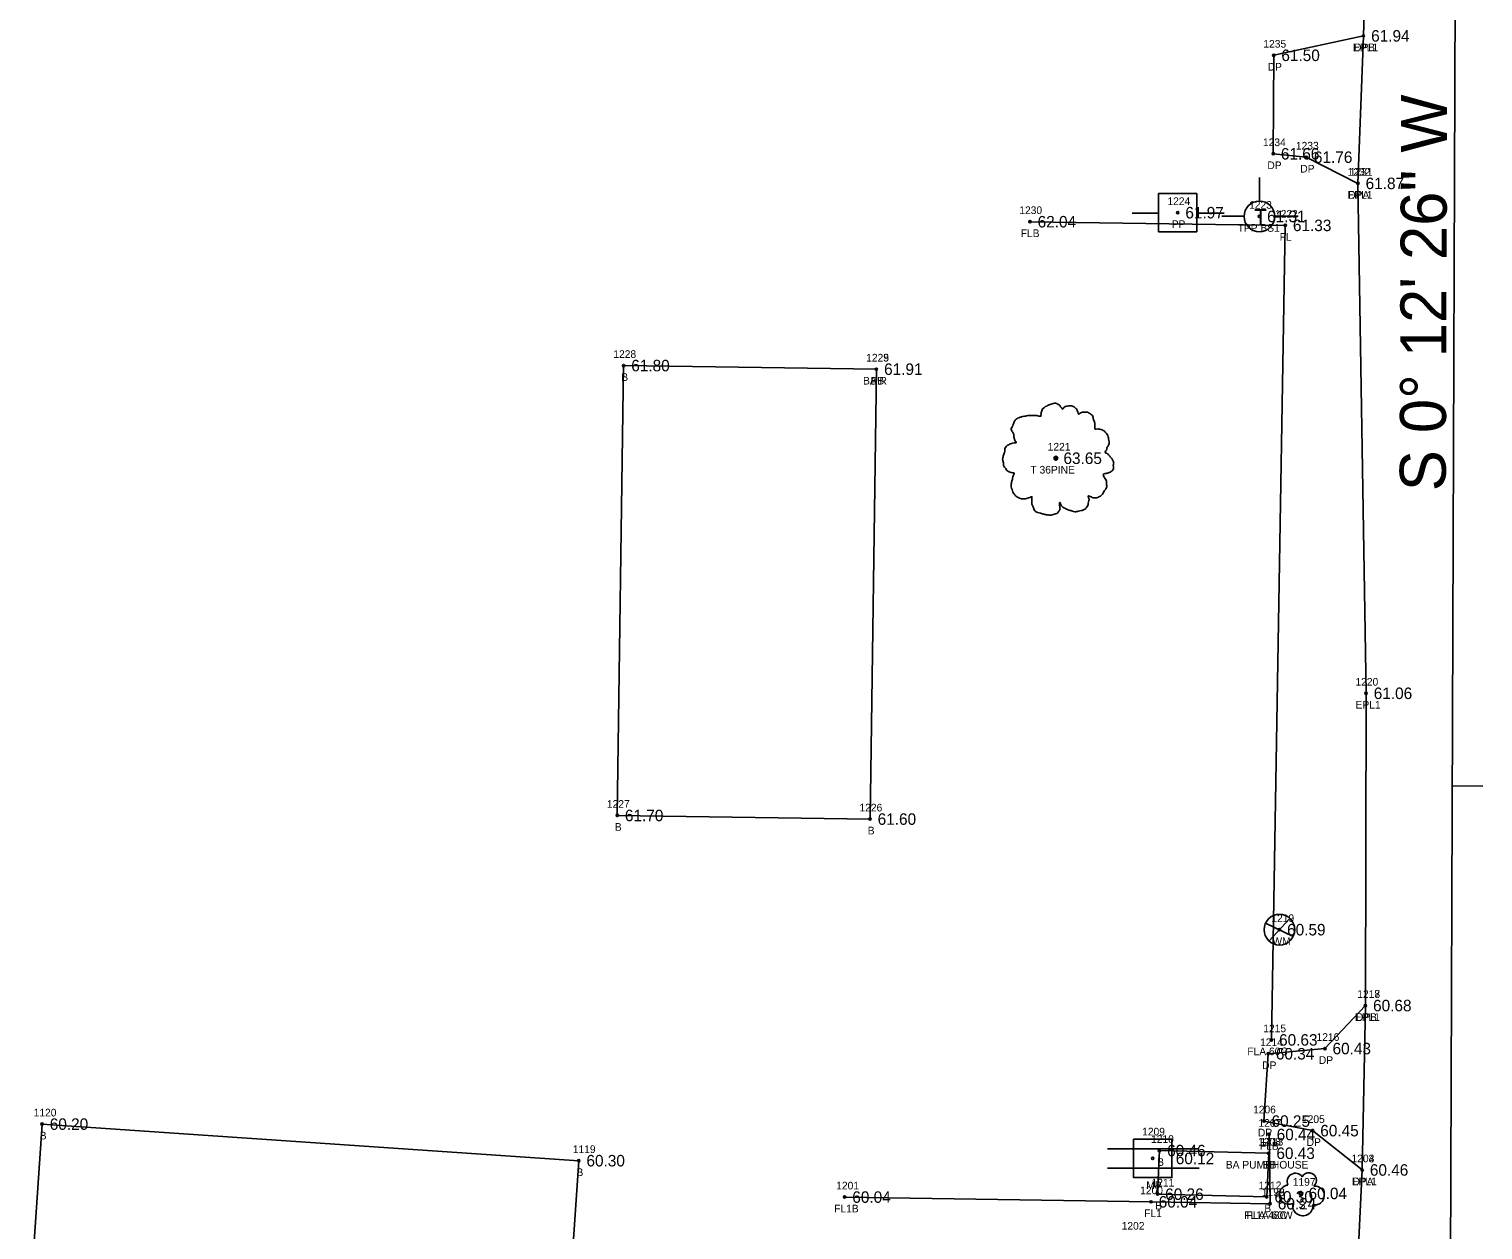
# Model space of a CAD drawing. Extents: x 2420113 to 2422887, y 845323 to 846653.
# Drawn here: x 2420774.1 to 2420963.9, y 845827.5 to 845984.2 of the extents above; entities that cross this region are included whole.
import ezdxf

# ---------------------------------------------------------------- set-up
doc = ezdxf.new("R2010")
doc.units = 0
for name, color, linetype in [('RD_EX_Bldg', 7, 'Continuous'), ('RD_EX_Bldg_txCode', 7, 'Continuous'), ('RD_EX_Driveway', 7, 'Continuous'), ('RD_EX_Driveway_txCode', 7, 'Continuous'), ('RD_EX_Fence_Other', 7, 'Continuous'), ('RD_EX_Fence_Other_txCode', 7, 'Continuous'), ('RD_EX_Road', 7, 'Continuous'), ('RD_EX_Road_txCode', 7, 'Continuous'), ('RD_EX_TX_Bldg_ELEV', 7, 'Continuous'), ('RD_EX_TX_Driveway_ELEV', 7, 'Continuous'), ('RD_EX_TX_Fence_Other_ELEV', 7, 'Continuous'), ('RD_EX_TX_Road_ELEV', 7, 'Continuous'), ('RD_EX_TX_UT_ELEV', 7, 'Continuous'), ('RD_EX_TX_VEG_ELEV', 7, 'Continuous'), ('RD_EX_UT', 7, 'Continuous'), ('RD_EX_UT_txCode', 7, 'Continuous'), ('RD_EX_VEG', 7, 'Continuous'), ('RD_EX_VEG_txCode', 7, 'Continuous'), ('RD_HC_Cl', 7, 'Continuous'), ('RD_HC_Data', 7, 'Continuous'), ('RD_HC_Data_Tic', 7, 'Continuous'), ('RD_HC_Survey_ELEV', 7, 'Continuous'), ('RD_SMD_Locator', 7, 'Continuous')]:
    doc.layers.add(name, color=color, linetype=linetype)

msp = doc.modelspace()

# ---------------------------------------------------------------- linework, layer by layer
at = {"layer": 'RD_EX_Bldg'}
for points in [[(2420884.74, 845939.79), (2420883.9, 845881.09), (2420850.91, 845881.56), (2420851.74, 845940.26), (2420884.74, 845939.79)], [(2420774.14, 845816.35), (2420844.19, 845811.58), (2420845.89, 845836.52), (2420775.84, 845841.29), (2420774.14, 845816.35)], [(2420935.94, 845837.49), (2420921.68, 845837.84), (2420921.43, 845832.15), (2420935.68, 845831.8), (2420935.94, 845837.49)]]:
    msp.add_lwpolyline(points, dxfattribs=at)
at = {"layer": 'RD_EX_Driveway'}
for points in [[(2420947.59, 845964.03), (2420940.84, 845967.45), (2420936.53, 845967.89), (2420936.59, 845980.74), (2420948.31, 845983.28)], [(2420948.14, 845835.31), (2420941.67, 845840.44), (2420935.31, 845841.69), (2420935.87, 845850.47), (2420943.27, 845851.15), (2420948.56, 845856.76)]]:
    msp.add_lwpolyline(points, dxfattribs=at)
at = {"layer": 'RD_EX_Fence_Other'}
msp.add_line((2420936.12, 845830.91), (2420935.98, 845839.94), dxfattribs=at)
for points in [[(2420936.29, 845852.28), (2420938.1, 845958.55), (2420904.78, 845959.03)], [(2420936.12, 845830.91), (2420920.58, 845831.15), (2420880.59, 845831.77)]]:
    msp.add_lwpolyline(points, dxfattribs=at)
at = {"layer": 'RD_EX_Road'}
msp.add_lwpolyline([(2420911.08, 845716.87), (2420926.22, 845723.04), (2420936.01, 845731.06), (2420942.67, 845742.11), (2420946.54, 845756.04), (2420945.56, 845775.49), (2420946.2, 845794.55), (2420948.14, 845835.31), (2420948.56, 845856.76), (2420948.65, 845897.5), (2420947.59, 845964.03), (2420948.31, 845983.28), (2420948.75, 845998.25), (2420949.7, 846105.56), (2420949.53, 846120.86), (2420949.28, 846141.3), (2420949.41, 846199.43)], dxfattribs=at)
at = {"layer": 'RD_EX_UT'}
for p, q in [((2420934.73, 845964.79), (2420934.73, 845961.72)), ((2420926.55, 845962.72), (2420921.55, 845962.72)), ((2420921.55, 845962.72), (2420921.55, 845957.72)), ((2420926.55, 845957.72), (2420926.55, 845962.72)), ((2420918.12, 845960.16), (2420921.59, 845960.16)), ((2420926.48, 845960.16), (2420930.12, 845960.16)), ((2420929.8, 845959.74), (2420932.73, 845959.74)), ((2420936.73, 845959.74), (2420939.8, 845959.74)), ((2420921.55, 845957.72), (2420926.55, 845957.72)), ((2420935.99, 845865.2), (2420938.65, 845868.09)), ((2420935.51, 845867.49), (2420939.14, 845865.78)), ((2420914.88, 845838.06), (2420926.88, 845838.06)), ((2420914.88, 845835.56), (2420926.88, 845835.56))]:
    msp.add_line(p, q, dxfattribs=at)
msp.add_lwpolyline([(2420918.31, 845839.31), (2420923.31, 845839.31), (2420923.31, 845834.31), (2420918.31, 845834.31)], close=True, dxfattribs=at)
for centre in [(2420934.73, 845959.72), (2420937.34, 845866.66)]:
    msp.add_circle(centre, 2, dxfattribs=at)
at = {"layer": 'RD_EX_VEG'}
for centre, radius in [((2420908.15, 845928.17), 0.25), ((2420908.14, 845928.15), 0.0001), ((2420940.14, 845832.25), 0.25)]:
    msp.add_circle(centre, radius, dxfattribs=at)
for centre, radius, start, end in [((2420939.42, 845833.8), 1.08, 34.9763, 204.756), ((2420941.19, 845833.95), 0.995, 308.7626, 152.0467), ((2420938.58, 845832.09), 1.26, 96.4518, 294.734), ((2420941.98, 845831.97), 1.22, 256.5667, 98.1046), ((2420940.39, 845830.65), 1.32, 166.8827, 5.7589)]:
    msp.add_arc(centre, radius, start, end, dxfattribs=at)
for points in [[(2420908.28, 845935.33), (2420907.98, 845935.36), (2420907.66, 845935.26), (2420907.41, 845935.16), (2420907.18, 845935.08), (2420906.96, 845934.98), (2420906.66, 845934.81), (2420906.43, 845934.61), (2420906.31, 845934.36), (2420906.26, 845934.13), (2420906.21, 845933.86), (2420906.21, 845933.68), (2420906.08, 845933.66), (2420905.93, 845933.68), (2420905.68, 845933.76), (2420905.43, 845933.76), (2420905.18, 845933.76), (2420904.83, 845933.73), (2420904.48, 845933.73), (2420904.21, 845933.68), (2420903.88, 845933.63), (2420903.51, 845933.51), (2420903.16, 845933.38), (2420902.86, 845933.13), (2420902.61, 845932.66), (2420902.48, 845932.31), (2420902.33, 845932.06), (2420902.48, 845931.61), (2420902.66, 845931.26), (2420902.68, 845931.06), (2420902.76, 845930.64), (2420902.86, 845930.41), (2420902.98, 845930.21), (2420902.91, 845930.19), (2420902.53, 845930.14), (2420902.23, 845930.04), (2420901.81, 845929.81), (2420901.59, 845929.59), (2420901.49, 845929.26), (2420901.46, 845928.91), (2420901.36, 845928.71), (2420901.29, 845928.44), (2420901.26, 845928.36), (2420901.21, 845928.04), (2420901.31, 845927.59), (2420901.34, 845927.24), (2420901.46, 845927.01), (2420901.61, 845926.84), (2420901.78, 845926.59), (2420902.18, 845926.36), (2420902.51, 845926.26), (2420902.71, 845926.24), (2420902.53, 845925.74), (2420902.48, 845925.39), (2420902.36, 845924.99), (2420902.36, 845924.91), (2420902.31, 845924.44), (2420902.46, 845924.11), (2420902.53, 845923.74), (2420902.71, 845923.51), (2420902.98, 845923.21), (2420903.31, 845922.99), (2420903.81, 845922.86), (2420904.21, 845922.89), (2420904.78, 845923.06), (2420905.03, 845923.14), (2420905.01, 845922.96), (2420905.03, 845922.59), (2420905.03, 845922.16), (2420905.18, 845921.84), (2420905.28, 845921.56), (2420905.43, 845921.31), (2420905.76, 845921.09), (2420906.16, 845921.01), (2420906.58, 845920.86), (2420907.03, 845920.79), (2420907.53, 845920.76), (2420908.13, 845920.91), (2420908.41, 845921.04), (2420908.51, 845921.21), (2420908.71, 845921.59), (2420908.66, 845921.81), (2420908.68, 845922.41), (2420908.78, 845922.24), (2420908.96, 845921.89), (2420909.46, 845921.59), (2420909.86, 845921.41), (2420910.33, 845921.26), (2420910.63, 845921.19), (2420911.11, 845921.26), (2420911.48, 845921.34), (2420911.86, 845921.46), (2420912.16, 845921.74), (2420912.33, 845922.01), (2420912.38, 845922.29), (2420912.46, 845922.66), (2420912.51, 845922.84)], [(2420912.51, 845922.84), (2420912.43, 845923.01), (2420912.38, 845923.26), (2420912.46, 845923.24), (2420912.63, 845923.19), (2420912.91, 845923.06), (2420913.13, 845922.99), (2420913.45, 845923.01), (2420913.73, 845923.11), (2420914.18, 845923.39), (2420914.45, 845923.86), (2420914.73, 845924.26), (2420914.8, 845924.59), (2420914.75, 845924.81), (2420914.73, 845925.31), (2420914.53, 845925.56), (2420914.48, 845925.69), (2420914.38, 845926.09), (2420914.45, 845926.14), (2420914.73, 845926.19), (2420915.1, 845926.31), (2420915.38, 845926.44), (2420915.6, 845926.61), (2420915.68, 845926.84), (2420915.65, 845927.24), (2420915.7, 845927.64), (2420915.63, 845927.79), (2420915.53, 845927.94), (2420915.45, 845928.14), (2420915.3, 845928.29), (2420915.2, 845928.44), (2420915.1, 845928.54), (2420914.98, 845928.69), (2420914.8, 845928.81), (2420914.65, 845928.86), (2420914.6, 845929.01), (2420914.75, 845929.21), (2420914.8, 845929.31), (2420914.83, 845929.54), (2420915.05, 845929.89), (2420915.1, 845930.29), (2420915.05, 845930.71), (2420915, 845930.98), (2420914.85, 845931.26), (2420914.65, 845931.51), (2420914.53, 845931.68), (2420914.35, 845931.81), (2420914.03, 845931.93), (2420913.78, 845931.98), (2420913.43, 845931.98), (2420913.23, 845932.03), (2420913.25, 845932.08), (2420913.25, 845932.23), (2420913.25, 845932.51), (2420913.18, 845932.96), (2420913.03, 845933.46), (2420913.03, 845933.48), (2420912.93, 845933.73), (2420912.71, 845933.93), (2420912.53, 845934.03), (2420912.33, 845934.16), (2420912.08, 845934.18), (2420911.78, 845934.18), (2420911.51, 845934.13), (2420911.31, 845934.03), (2420911.13, 845933.91), (2420911.06, 845934.06), (2420910.96, 845934.36), (2420910.91, 845934.51), (2420910.76, 845934.68), (2420910.53, 845934.88), (2420910.08, 845935.01), (2420909.46, 845934.93), (2420909.16, 845934.73), (2420909.01, 845934.56), (2420908.96, 845934.68), (2420908.76, 845934.88), (2420908.66, 845935.06), (2420908.48, 845935.18), (2420908.33, 845935.28), (2420908.23, 845935.33)]]:
    msp.add_spline(points, degree=3, dxfattribs=at)
at = {"layer": 'RD_HC_Cl'}
msp.add_line((2420961.04, 846199.81), (2420959.23, 845699.82), dxfattribs=at)
at = {"layer": 'RD_HC_Data_Tic'}
msp.add_line((2420959.9, 845885.41), (2420963.9, 845885.4), dxfattribs=at)
at = {"layer": 'RD_SMD_Locator'}
for centre in [(2420948.31, 845983.28), (2420948.31, 845983.28), (2420936.59, 845980.74), (2420936.53, 845967.89), (2420940.84, 845967.45), (2420947.59, 845964.03), (2420947.59, 845964.03), (2420904.78, 845959.03), (2420924.06, 845960.21), (2420934.73, 845959.72), (2420938.1, 845958.55), (2420851.74, 845940.26), (2420884.74, 845939.79), (2420884.74, 845939.79), (2420908.15, 845928.17), (2420948.65, 845897.5), (2420850.91, 845881.56), (2420883.9, 845881.09), (2420937.34, 845866.66), (2420948.56, 845856.76), (2420948.56, 845856.76), (2420936.29, 845852.28), (2420943.27, 845851.15), (2420935.87, 845850.47), (2420775.84, 845841.29), (2420935.31, 845841.69), (2420935.98, 845839.94), (2420941.67, 845840.44), (2420921.68, 845837.84), (2420935.94, 845837.49), (2420935.94, 845837.49), (2420845.89, 845836.52), (2420920.81, 845836.81), (2420948.14, 845835.31), (2420948.14, 845835.31), (2420880.59, 845831.77), (2420921.43, 845832.15), (2420935.68, 845831.8), (2420940.14, 845832.25), (2420920.58, 845831.15), (2420936.12, 845830.91), (2420936.12, 845830.91)]:
    msp.add_circle(centre, 0.15, dxfattribs=at)

# ---------------------------------------------------------------- texts
at = {"layer": 'RD_EX_Bldg_txCode'}
for s, p in [('1228', (2420850.4, 845941.26)), ('1225', (2420883.4, 845940.79)), ('1229', (2420883.4, 845940.79)), ('B', (2420851.44, 845938.26)), ('BA R', (2420882.99, 845937.79)), ('BB', (2420883.96, 845937.79)), ('1227', (2420849.56, 845882.56)), ('1226', (2420882.53, 845882.09)), ('B', (2420850.6, 845879.56)), ('B', (2420883.6, 845879.09)), ('1120', (2420774.74, 845842.29)), ('B', (2420775.53, 845839.29)), ('1210', (2420920.58, 845838.84)), ('1208', (2420934.55, 845838.49)), ('1213', (2420934.87, 845838.49)), ('1119', (2420845.11, 845837.52)), ('B', (2420921.38, 845835.84)), ('BA PUMPHOUSE', (2420930.34, 845835.49)), ('BB', (2420935.16, 845835.49)), ('B', (2420845.59, 845834.52)), ('1211', (2420920.65, 845833.15)), ('1212', (2420934.62, 845832.8)), ('B', (2420921.12, 845830.15)), ('B', (2420935.37, 845829.8))]:
    msp.add_text(s, height=1, dxfattribs=at).set_placement(p)
at = {"layer": 'RD_EX_Driveway_txCode'}
for s, p in [('1235', (2420935.24, 845981.74)), ('DPB', (2420947.06, 845981.28)), ('DP', (2420935.81, 845978.74)), ('1234', (2420935.19, 845968.89)), ('1233', (2420939.49, 845968.45)), ('DP', (2420935.76, 845965.89)), ('DP', (2420940.06, 845965.45)), ('1232', (2420946.24, 845965.03)), ('DPA', (2420946.32, 845962.03)), ('1217', (2420947.5, 845857.76)), ('DPB', (2420947.31, 845854.76)), ('1216', (2420942.18, 845852.15)), ('1214', (2420934.81, 845851.47)), ('DP', (2420935.09, 845848.47)), ('DP', (2420942.49, 845849.15)), ('1206', (2420933.9, 845842.69)), ('1205', (2420940.28, 845841.44)), ('DP', (2420934.53, 845839.69)), ('DP', (2420940.89, 845838.44)), ('1204', (2420946.75, 845836.31)), ('DPA', (2420946.87, 845833.31))]:
    msp.add_text(s, height=1, dxfattribs=at).set_placement(p)
at = {"layer": 'RD_EX_Fence_Other_txCode'}
for s, p in [('1230', (2420903.39, 845960.03)), ('1222', (2420936.76, 845959.55)), ('FLB', (2420903.57, 845957.03)), ('FL', (2420937.37, 845956.55)), ('1215', (2420935.23, 845853.28)), ('FLA 60C', (2420933.15, 845850.28)), ('1207', (2420934.6, 845840.94)), ('FLB', (2420934.78, 845837.94)), ('1201', (2420879.49, 845832.77)), ('1200', (2420919.16, 845832.15)), ('1198', (2420935.05, 845831.91)), ('1199', (2420935.05, 845831.91)), ('FL1B', (2420879.22, 845829.77)), ('FL1', (2420919.69, 845829.15)), ('FL1A 60W', (2420932.75, 845828.91)), ('FLA 48C', (2420933.04, 845828.91))]:
    msp.add_text(s, height=1, dxfattribs=at).set_placement(p)
at = {"layer": 'RD_EX_Road_txCode'}
for s, p in [('EPL1', (2420946.94, 845981.28)), ('1231', (2420946.52, 845965.03)), ('EPL1', (2420946.22, 845962.03)), ('1220', (2420947.26, 845898.5)), ('EPL1', (2420947.28, 845895.5)), ('1218', (2420947.5, 845857.76)), ('EPL1', (2420947.19, 845854.76)), ('1203', (2420946.75, 845836.31)), ('EPL1', (2420946.77, 845833.31))]:
    msp.add_text(s, height=1, dxfattribs=at).set_placement(p)
at = {"layer": 'RD_EX_TX_Bldg_ELEV'}
for s, p in [('61.80', (2420852.74, 845939.51)), ('61.91', (2420885.74, 845939.04)), ('61.91', (2420885.74, 845939.04)), ('61.70', (2420851.91, 845880.81)), ('61.60', (2420884.9, 845880.34)), ('60.20', (2420776.84, 845840.54)), ('60.46', (2420922.68, 845837.09)), ('60.43', (2420936.94, 845836.74)), ('60.43', (2420936.94, 845836.74)), ('60.30', (2420846.89, 845835.77)), ('60.26', (2420922.43, 845831.4)), ('60.30', (2420936.68, 845831.05))]:
    msp.add_text(s, height=1.5, dxfattribs=at).set_placement(p)
at = {"layer": 'RD_EX_TX_Driveway_ELEV'}
for s, p in [('61.94', (2420949.31, 845982.53)), ('61.50', (2420937.59, 845979.99)), ('61.66', (2420937.53, 845967.14)), ('61.76', (2420941.84, 845966.7)), ('61.87', (2420948.59, 845963.28)), ('60.68', (2420949.56, 845856.01)), ('60.34', (2420936.87, 845849.72)), ('60.43', (2420944.27, 845850.4)), ('60.25', (2420936.31, 845840.94)), ('60.45', (2420942.67, 845839.69)), ('60.46', (2420949.14, 845834.56))]:
    msp.add_text(s, height=1.5, dxfattribs=at).set_placement(p)
at = {"layer": 'RD_EX_TX_Fence_Other_ELEV'}
for s, p in [('62.04', (2420905.78, 845958.28)), ('61.33', (2420939.1, 845957.8)), ('60.63', (2420937.29, 845851.53)), ('60.44', (2420936.98, 845839.19)), ('60.04', (2420881.59, 845831.02)), ('60.04', (2420921.58, 845830.4)), ('60.24', (2420937.12, 845830.16)), ('60.24', (2420937.12, 845830.16))]:
    msp.add_text(s, height=1.5, dxfattribs=at).set_placement(p)
at = {"layer": 'RD_EX_TX_Road_ELEV'}
for s, p in [('61.94', (2420949.31, 845982.53)), ('61.87', (2420948.59, 845963.28)), ('61.06', (2420949.65, 845896.75)), ('60.68', (2420949.56, 845856.01)), ('60.46', (2420949.14, 845834.56))]:
    msp.add_text(s, height=1.5, dxfattribs=at).set_placement(p)
at = {"layer": 'RD_EX_TX_UT_ELEV'}
for s, p in [('61.31', (2420935.73, 845958.97)), ('60.59', (2420938.34, 845865.91)), ('60.12', (2420923.81, 845836.06))]:
    msp.add_text(s, height=1.5, dxfattribs=at).set_placement(p)
at = {"layer": 'RD_EX_TX_VEG_ELEV'}
for s, p in [('63.65', (2420909.15, 845927.42)), ('60.04', (2420941.14, 845831.5))]:
    msp.add_text(s, height=1.5, dxfattribs=at).set_placement(p)
at = {"layer": 'RD_EX_UT'}
msp.add_text('T', height=2, dxfattribs=at).set_placement((2420934.06, 845958.67))
at = {"layer": 'RD_EX_UT_txCode'}
for s, p in [('1224', (2420922.72, 845961.21)), ('1223', (2420933.38, 845960.72)), ('PP', (2420923.28, 845958.21)), ('TPP BS1', (2420931.88, 845957.72)), ('1219', (2420936.28, 845867.66)), ('WM', (2420936.43, 845864.66)), ('1209', (2420919.42, 845839.81)), ('MP', (2420919.96, 845832.81))]:
    msp.add_text(s, height=1, dxfattribs=at).set_placement(p)
at = {"layer": 'RD_EX_VEG_txCode'}
for s, p in [('1221', (2420907.09, 845929.17)), ('T 36PINE', (2420904.84, 845926.17)), ('1197', (2420939.08, 845833.25)), ('S', (2420939.84, 845830.25)), ('1202', (2420916.75, 845827.52))]:
    msp.add_text(s, height=1, dxfattribs=at).set_placement(p)
at = {"layer": 'RD_HC_Data'}
msp.add_text('S 0%%d 12\' 26" W', height=6, rotation=89.7927, dxfattribs=at).set_placement((2420959.04, 845923.86))
at = {"layer": 'RD_HC_Survey_ELEV'}
msp.add_text('61.97', height=1.5, dxfattribs=at).set_placement((2420925.06, 845959.46))

doc.saveas('drawing.dxf')
